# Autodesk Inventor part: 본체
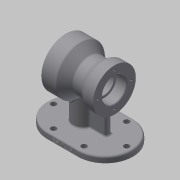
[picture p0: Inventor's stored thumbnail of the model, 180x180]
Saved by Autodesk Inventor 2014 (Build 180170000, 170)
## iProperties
Created: 2020-01
Part Number: 본체
Material: Generic
Document SubType Name: Modeling
Designer: kh
Density: 1 g/cm^3
Appearance: Default
Author: kh
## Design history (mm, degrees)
sketch "Sketch1"
  geometry: L1 (25, 45)-(-25, 45); L2 (-25, 45)-(-25, -45); L3 (-25, -45)-(25, -45); L4 (25, -45)-(25, 45); L5 (25, 45)-(-25, -45); L6 (-25, 45)-(25, -45); L7 (0, 0)-(-25, 0); C1 r 45 at (-25, 0); C2 r 45 at (25, 0); 1 further point
  constraints: 14 end point, 4 midpoint, 2 centre point, 2 coincident, 2 parallel, 2 perpendicular, 1 horizontal
  dimensions: "d0" = 50 distance of L1.start L1.end; "d1" = 90 distance of L1.end L2.end; "d2" = 90 diameter of C1; "d3" = 90 diameter of C2
extrude "Extrusion1" new body sketch "Sketch1" distance "d4" = 10; taper "d5" = 0 deg
sketch "Sketch2"
  geometry: L1 (0, 0)-(0, 80); L2 (118.837, 80)-(-118.837, 80); L3 (40, 80)-(40, 120); L4 (40, 120)-(16, 120); L5 (16, 120)-(1.103, 107.5); L6 (1.103, 107.5)-(-13.289, 107.5); L7 (-13.289, 107.5)-(-24, 115); L8 (-24, 115)-(-40, 115); L9 (-40, 115)-(-40, 80); L10 (40, 80)-(-40, 80); L11 (70, 0)-(70, 10) reference; L12 (-70, 0)-(-70, 10) reference; L13 (-30, 80)-(-30, -1.918)
  constraints: 22 end point, 6 perpendicular, 3 point on line, 2 parallel, 1 midpoint, 1 vertical
  dimensions: "d6" = 80 distance of L1.end L1.start; "d7" = 24 distance of L3.end L4.end; "d8" = 16 distance of L7.end L8.end; "d9" = 80 distance between parallel lines of L9 L3; "d10" = 55 diameter of L6 L2; "d11" = 80 diameter of L4 L2; "d12" = 70 diameter of L8 L2; "d13" = 30 horizontal distance of L11.start L3.start; "d14" = 10 distance between parallel lines of L13 L9; "d15" = 40 deg angle of L6 L5; "d16" = 35 deg angle of L7 L6
revolve "Revolution1" sketch "Sketch2" stored, may be unused: angle "d17" = 90 deg
sketch "Sketch3"
  geometry: L1 (-25, -45)-(25, -45) reference; L2 (-70, 0)-(76.908, 0); L3 (30, 5)-(-9.895, 5); L4 (-9.895, 5)-(-9.895, -5); L5 (-9.895, -5)-(30, -5); L6 (30, -5)-(30, 5); L7 (30, 5)-(-9.895, -5); L8 (-9.895, 5)-(30, -5); L9 (40, 35)-(40, -35) reference; C1 r 16 at (-12, 0); A1 r 45 centre (-25, 0) between (-25, 45) and (-25, -45) reference; A2 r 45 centre (-25, 0) between (-25, 45) and (-25, -45) reference; 2 further points
  constraints: 14 end point, 3 parallel, 2 midpoint, 1 centre point, 1 horizontal, 1 horizontal alignment, 1 perpendicular, 1 point on circle, 1 point on line
  dimensions: "d36" = 58 distance of L2.start C1.centre; "d37" = 10 distance of L5.end L3.start; "d38" = 10 horizontal distance of L5.end L9.end; "d85" = 32 diameter of C1
extrude "Extrusion2" join sketch "Sketch3" distance "d39" = 80; taper "d40" = 0 deg
hole "Hole1" diameter "d20" = 32; stored, may be unused: countersink angle "d24" = 90 deg, drill point angle "d26" = 0 deg; dims "d18" = 10, "d19" = 10, "d21" = 6, "d22" = 40, "d23" = 17, "d25" = 8
hole "Hole2" diameter "d29" = 52; stored, may be unused: countersink angle "d33" = 90 deg, drill point angle "d35" = 0 deg; dims "d27" = 10, "d28" = 10, "d30" = 6, "d31" = 40, "d32" = 17, "d34" = 20
sketch "Sketch4"
  geometry: L1 (0, 0)-(50, 0) reference; 3 further points
  constraints: 1 midpoint, 1 vertical alignment, 1 other
  dimensions: "d81" = 4 distance of point (25, 4) point (25, 0)
emboss "Emboss1" sketch "Sketch4" dims "d41" = 0.5, "d42" = 0
sketch "Sketch5"
  geometry: C1 r 20 at (0, 0) reference; 2 further points
  constraints: 1 horizontal alignment
  dimensions: "d43" = 27.5 distance of point (-27.5, 0) C1.centre
hole "Hole3" sketch "Sketch5" at (-27.5, 0) diameter "d44" = 3.242; stored, may be unused: countersink angle "d48" = 90 deg, drill point angle "d50" = 118 deg; dims "d45" = 9, "d46" = 40, "d47" = 17, "d49" = 11
pattern_circular "Circular Pattern1" dims angle "d52" = 360 deg
sketch "Sketch6"
  geometry: C1 r 26 at (0, 0) reference; 2 further points
  constraints: 1 horizontal alignment
  dimensions: "d54" = 33 distance of C1.centre point (33, 0)
hole "Hole4" sketch "Sketch6" at (33, 0) diameter "d55" = 3.242; stored, may be unused: countersink angle "d59" = 90 deg, drill point angle "d61" = 118 deg; dims "d56" = 9, "d57" = 40, "d58" = 17, "d60" = 11
pattern_circular "Circular Pattern2" dims angle "d63" = 360 deg
chamfer "Chamfer1" distance "d65" = 1; stored, may be unused: second distance "d66" = 2, angle "d67" = 45 deg
fillet "Fillet1" dims "d68" = 0.3
fillet "Fillet2" dims "d69" = 3
sketch "Sketch7"
  geometry: L1 (27, -5)-(5.234, -5) reference; L2 (0, 0)-(0, 43.524); L3 (-12, 0)-(80.521, 0); L4 (0, 0)-(-70, 0); L5 (0, 0)-(70, 0); C1 r 4.5 at (-25, 35); C2 r 4.5 at (25, 35); C3 r 4.5 at (-25, -35); C4 r 4.5 at (25, -35); C5 r 4.5 at (-60, 0); C6 r 4.5 at (60, 0); A1 r 45 centre (25, 0) between (25, -45) and (25, 45) reference; A2 r 45 centre (-25, 0) between (-25, 45) and (-25, -45) reference; A3 r 16 centre (-12, 0) between (2.513, 6.737) and (2.513, -6.737) reference
  constraints: 8 end point, 6 centre point, 2 horizontal alignment, 2 perpendicular, 2 point on circle, 2 point on line, 2 symmetric about line, 1 vertical alignment, 2 other
  dimensions: "d70" = 9 diameter of C1; "d71" = 9 diameter of C2; "d72" = 50 distance of C2.centre C1.centre; "d73" = 10 distance of A2.start C1.centre; "d75" = 9 diameter of C5; "d76" = 10 distance of L4.end C5.centre; "d77" = 9 diameter of C6; "d78" = 10 distance of L5.end C6.centre
extrude "Extrusion3" cut sketch "Sketch7" distance "d79" = 80; taper "d80" = 0 deg
fillet "Fillet3" dims "d82" = 3
fillet "Fillet4" dims "d83" = 3
fillet "Fillet5" dims "d84" = 3
body "Solid1"
